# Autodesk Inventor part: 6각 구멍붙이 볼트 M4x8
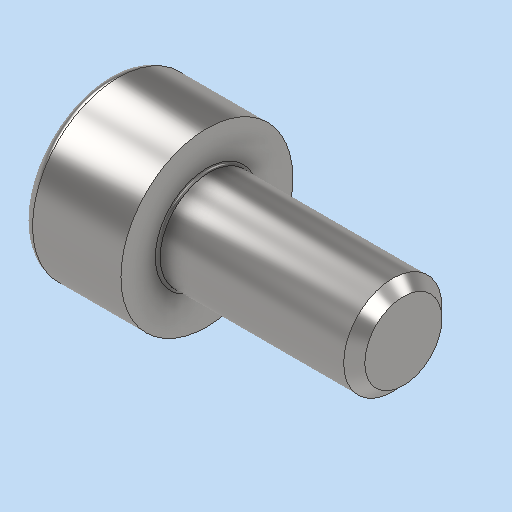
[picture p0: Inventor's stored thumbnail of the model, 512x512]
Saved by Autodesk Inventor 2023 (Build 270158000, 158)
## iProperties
Created: 2026-06
Part Number: 6각 구멍붙이 볼트 M4x8
Material: 강철, 연강
Description: 6각머리 태핑 나사
Document SubType Name: Modeling
Designer: home
Density: 7.85 g/cm^3
Appearance: 기본값
Sending System: Autodesk Inventor 2027
Preprocessor: ST-DEVELOPER v20.1
Author: jhkim
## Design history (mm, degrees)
feature "Solid1"
node "솔리드1"
